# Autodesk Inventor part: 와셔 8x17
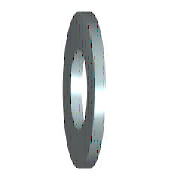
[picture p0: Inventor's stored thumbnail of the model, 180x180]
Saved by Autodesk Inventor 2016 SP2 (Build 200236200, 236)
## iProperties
IsCustomPart: 1
Created: 2012-02
Part Number: 와셔 8x17
Material: 강철, 연강
Description: 평면 와셔
Document SubType Name: Modeling
Standard: KS B 1326
Designer: mduedu
Standards Organization: KS
Language: ko-KR
Size Designation: 8x17
Categories: <MemberInstance><Categories><Category DisplayName="조임쇠" InternalName="e4da775c-781d-43d5-af7c-5136215cf5a6" Mnemonic="FSTN"><Category DisplayName="와셔" InternalN
Density: 1 g/cm^3
Appearance: 주황색
Author: mduedu
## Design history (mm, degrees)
sketch "스케치"
  geometry: C1 r 8.5 at (0, 0); C2 r 4.2 at (0, 0); 1 further point
  constraints: 2 centre point, 2 coincident
  dimensions: "d0" = 8.4 diameter of C2 (= SD1); "d1" = 17 diameter of C1 (= SD2)
extrude "본체" new body sketch "스케치" distance "d2" = 1.6 (= SD); taper "d3" = 0 deg
workaxis "Work Axis1"
workplane "Work Plane1"
body "Solid1"
other parameters: "SD1" = 8.4 [user parameter; used in 1 equation term], "SD2" = 17 [user parameter; used in 1 equation term], "SD" = 1.6 [user parameter; used in 1 equation term], "d4" = 0, "d5" = 0, "d6" = 0, "d7" = 0, "NND" = 8 [user parameter]
